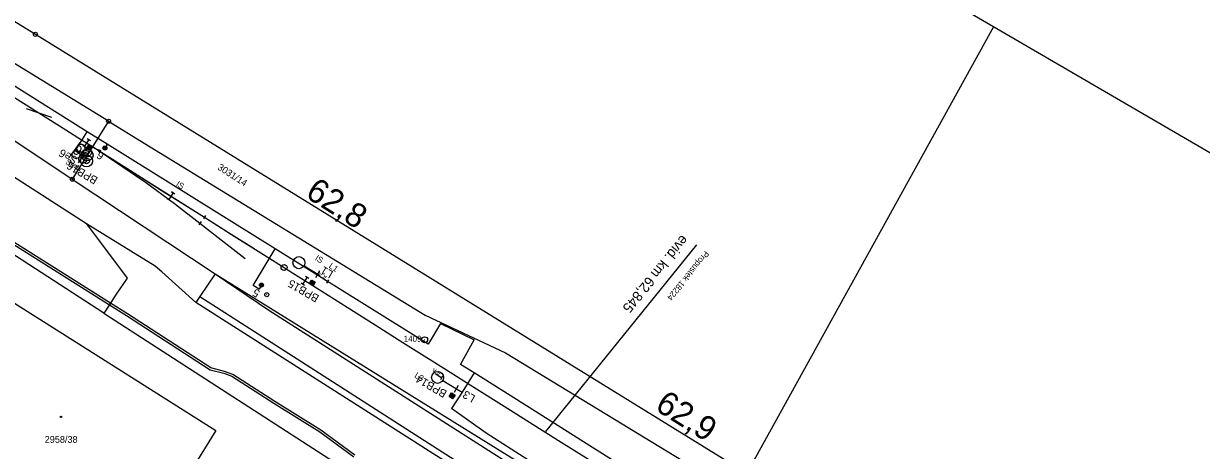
# Model space of a CAD drawing. Extents: x -621168 to -620292, y -1122748 to -1122069.
# Drawn here: x -620869 to -620574.6, y -1122402.8 to -1122296.3 of the extents above; entities that cross this region are included whole.
import ezdxf

# ---------------------------------------------------------------- set-up
doc = ezdxf.new("R2010")
doc.units = 0
for name, color, linetype in [('HranDP', 7, 'Continuous'), ('Hranice parcel', 7, 'Continuous'), ('Parcelní čísla', 7, 'Continuous'), ('Rámečky-tisk', 7, 'Continuous'), ('Vnitřní kresba', 7, 'Continuous'), ('Vrstva 1', 7, 'Continuous'), ('Vrstva 19', 7, 'Continuous'), ('Vrstva 2', 7, 'Continuous'), ('Vrstva 3', 7, 'Continuous'), ('Vrstva 6', 7, 'Continuous'), ('Vrstva 7', 7, 'Continuous'), ('Věcná břemena k části', 7, 'Continuous'), ('Značky bodu BP', 7, 'Continuous'), ('Značky budov', 7, 'Continuous')]:
    doc.layers.add(name, color=color, linetype=linetype)

msp = doc.modelspace()

# ---------------------------------------------------------------- linework, layer by layer
at = {"layer": 'HranDP'}
msp.add_line((-620856.79, -1122335.14), (-620821.12, -1122358.76), dxfattribs=at)
for points in [[(-620847.72, -1122320.67), (-620907.48, -1122284.08), (-620974.87, -1122244.96), (-620982.44, -1122240.65)], [(-620902.62, -1122306.44), (-620882.26, -1122318.28), (-620856.79, -1122335.14)], [(-620847.72, -1122320.67), (-620838.83, -1122326.12), (-620768.63, -1122369.09), (-620748.53, -1122378.52), (-620702.13, -1122406.7), (-620691.02, -1122413.66), (-620638.48, -1122446.57), (-620552.09, -1122499.2)], [(-620821.12, -1122358.76), (-620741.46, -1122408.09), (-620679.51, -1122447.56), (-620545.92, -1122532.26), (-620521.41, -1122548.27), (-620511.29, -1122557.64)]]:
    msp.add_lwpolyline(points, dxfattribs=at)
at = {"layer": 'Hranice parcel'}
for p, q in [((-620976.86, -1122231), (-620866.03, -1122298.98)), ((-620866.03, -1122298.98), (-620688.16, -1122408.5)), ((-620848.87, -1122368.55), (-620933.94, -1122313.6)), ((-620853.22, -1122346.25), (-620894.54, -1122319.77)), ((-620847.72, -1122320.67), (-620856.79, -1122335.14)), ((-620856.79, -1122335.14), (-620821.12, -1122358.76))]:
    msp.add_line(p, q, dxfattribs=at)
for points in [[(-620847.72, -1122320.67), (-620907.48, -1122284.08), (-620974.87, -1122244.96), (-620982.44, -1122240.65)], [(-620626.55, -1122297.1), (-620688.16, -1122408.5)], [(-620902.62, -1122306.44), (-620882.26, -1122318.28), (-620856.79, -1122335.14)], [(-620847.72, -1122320.67), (-620838.83, -1122326.12), (-620768.63, -1122369.09), (-620748.53, -1122378.52), (-620702.13, -1122406.7), (-620691.02, -1122413.66), (-620638.48, -1122446.57), (-620552.09, -1122499.2)], [(-620825.92, -1122365.89), (-620834.44, -1122358.28), (-620836.04, -1122356.85), (-620853.22, -1122346.25)], [(-620853.22, -1122346.25), (-620843.09, -1122359.81), (-620845.8, -1122363.88), (-620848.5, -1122367.99), (-620848.87, -1122368.55)], [(-620929.94, -1122378.34), (-620913.46, -1122352.29), (-620887.98, -1122368.3), (-620877.81, -1122374.71), (-620872.17, -1122365.51), (-620820.94, -1122397.9), (-620826.62, -1122407), (-620821.36, -1122410.31), (-620837.94, -1122436.41), (-620904.18, -1122394.6), (-620929.94, -1122378.34)], [(-620821.12, -1122358.76), (-620824.91, -1122364.39), (-620825.92, -1122365.89)], [(-620821.12, -1122358.76), (-620741.46, -1122408.09), (-620679.51, -1122447.56), (-620545.92, -1122532.26), (-620521.41, -1122548.27), (-620511.29, -1122557.64)], [(-620821.12, -1122358.76), (-620807.67, -1122367.84), (-620645.72, -1122471.03), (-620587.17, -1122509.18), (-620511.29, -1122557.64)], [(-620557.45, -1122536.96), (-620684.91, -1122455.63), (-620825.92, -1122365.89)], [(-620848.87, -1122368.55), (-620781.81, -1122411.87), (-620814.37, -1122462.27), (-620846.85, -1122512.55)]]:
    msp.add_lwpolyline(points, dxfattribs=at)
at = {"layer": 'Rámečky-tisk'}
msp.add_lwpolyline([(-620441.66, -1122748.16), (-620292.37, -1122491.41), (-621018.54, -1122069.17)], dxfattribs=at)
at = {"layer": 'Vnitřní kresba'}
for p, q in [((-620824.91, -1122364.39), (-620810.36, -1122373.73)), ((-620810.36, -1122373.73), (-620648.08, -1122477.56))]:
    msp.add_line(p, q, dxfattribs=at)
at = {"layer": 'Vrstva 1'}
for p, q in [((-620856.02, -1122328.01), (-620853.07, -1122323.34)), ((-620848.09, -1122326.43), (-620853.07, -1122323.34)), ((-620856.02, -1122328.01), (-620854.72, -1122328.89)), ((-620806.11, -1122352.53), (-620848.09, -1122326.43)), ((-620811.62, -1122361.65), (-620806.11, -1122352.53)), ((-620764.72, -1122371.2), (-620756.35, -1122375.21)), ((-620756.33, -1122383.52), (-620759.35, -1122388.27)), ((-620760.76, -1122387.45), (-620759.35, -1122388.27)), ((-620759.35, -1122388.27), (-620761.98, -1122392.4))]:
    msp.add_line(p, q, dxfattribs=at)
for points in [[(-620853.07, -1122323.34), (-620895.69, -1122296.63), (-620912.11, -1122286.23)], [(-620874.8, -1122312.5), (-620868.33, -1122316.57), (-620865.13, -1122318.58), (-620858.38, -1122322.84), (-620854.48, -1122325.28), (-620853.21, -1122326.08), (-620851.73, -1122327.01), (-620850.55, -1122327.76), (-620840.58, -1122334.05), (-620833.63, -1122338.43), (-620832.14, -1122339.37), (-620823.78, -1122344.63), (-620817.74, -1122348.46), (-620811.37, -1122352.45)], [(-620854.72, -1122328.89), (-620855.09, -1122329.44), (-620854.51, -1122329.81)], [(-620851.64, -1122327.08), (-620843.14, -1122332.43), (-620837.63, -1122335.92), (-620832.12, -1122339.39), (-620828.02, -1122341.97), (-620823.79, -1122344.63), (-620816.97, -1122348.94), (-620810.35, -1122353.09), (-620803.86, -1122357.18), (-620803.36, -1122357.5), (-620800.13, -1122359.53), (-620798.65, -1122360.46), (-620794.42, -1122363.12), (-620788.1, -1122367.1), (-620781.12, -1122371.5), (-620774.17, -1122375.88), (-620767.51, -1122380.06), (-620763.22, -1122382.76), (-620756.39, -1122387.05), (-620748.87, -1122391.78), (-620741.59, -1122396.35), (-620734.61, -1122400.75), (-620727.79, -1122405.03)], [(-620850.55, -1122327.76), (-620838.47, -1122335.9), (-620831.26, -1122341.18), (-620824.88, -1122346.1), (-620819.56, -1122350.3), (-620813.61, -1122354.97)], [(-620848.09, -1122326.43), (-620848.09, -1122326.43), (-620848.63, -1122327.36)], [(-620795.27, -1122359.26), (-620795.68, -1122359.01), (-620806.11, -1122352.53)], [(-620795.42, -1122358.82), (-620795.12, -1122359.01), (-620795.27, -1122359.26)], [(-620764.72, -1122371.2), (-620767.85, -1122376.3), (-620794.6, -1122359.68), (-620795.27, -1122359.26)], [(-620809.51, -1122361.58), (-620810.11, -1122362.57), (-620811.62, -1122361.65)], [(-620756.33, -1122383.52), (-620759.75, -1122381.36), (-620756.35, -1122375.21)], [(-620538.89, -1122521.21), (-620599.21, -1122483.22), (-620683.52, -1122429.44), (-620747.38, -1122389.13), (-620756.33, -1122383.52)], [(-620738.73, -1122407.89), (-620753.37, -1122398.54), (-620761.98, -1122392.4)]]:
    msp.add_lwpolyline(points, dxfattribs=at)
at = {"layer": 'Vrstva 19'}
msp.add_line((-620700.78, -1122351.5), (-620738.53, -1122398.14), dxfattribs=at)
at = {"layer": 'Vrstva 2'}
for p, q in [((-620853.74, -1122328.53), (-620855.29, -1122331.09)), ((-620852.78, -1122328.69), (-620854.51, -1122329.09)), ((-620852.5, -1122328.24), (-620854.45, -1122328.69)), ((-620852.38, -1122327.83), (-620854.23, -1122328.25)), ((-620852.28, -1122327.88), (-620853.83, -1122330.36)), ((-620853.2, -1122327.4), (-620851.84, -1122327.07)), ((-620853.13, -1122327.52), (-620851.85, -1122327.21)), ((-620853.1, -1122327.25), (-620852, -1122326.97)), ((-620853.01, -1122327.09), (-620852.16, -1122326.88)), ((-620852.97, -1122327.62), (-620851.95, -1122327.37)), ((-620852.91, -1122326.93), (-620852.32, -1122326.78)), ((-620852.82, -1122326.77), (-620852.48, -1122326.69)), ((-620852.81, -1122327.71), (-620852.05, -1122327.52)), ((-620852.72, -1122326.61), (-620852.64, -1122326.59)), ((-620852.65, -1122327.81), (-620852.14, -1122327.68)), ((-620852.49, -1122327.91), (-620852.24, -1122327.84)), ((-620852.28, -1122327.88), (-620851.73, -1122327.01)), ((-620852.28, -1122327.88), (-620852.28, -1122327.88)), ((-620848.14, -1122327.31), (-620849.13, -1122327.42)), ((-620848.2, -1122327.11), (-620849.11, -1122327.21)), ((-620848.16, -1122327.51), (-620849.07, -1122327.61)), ((-620848.38, -1122326.93), (-620848.97, -1122327)), ((-620848.29, -1122327.73), (-620848.88, -1122327.79)), ((-620853.07, -1122329.14), (-620854.47, -1122329.46)), ((-620853.35, -1122329.59), (-620854.34, -1122329.82)), ((-620853.63, -1122330.04), (-620854.09, -1122330.15)), ((-620824.58, -1122345.71), (-620825.19, -1122346.5)), ((-620823.51, -1122344.21), (-620824.04, -1122345.06)), ((-620798.85, -1122356.75), (-620795.42, -1122358.82)), ((-620795.94, -1122359.68), (-620794.91, -1122357.96)), ((-620809.82, -1122361.18), (-620809.6, -1122362.07)), ((-620809.63, -1122361.09), (-620809.39, -1122362.06)), ((-620809.43, -1122361.09), (-620809.21, -1122361.97)), ((-620809.2, -1122361.19), (-620809.05, -1122361.77)), ((-620796.1, -1122360.91), (-620797.46, -1122361.25)), ((-620796.18, -1122360.8), (-620797.45, -1122361.11)), ((-620796.33, -1122360.7), (-620797.35, -1122360.95)), ((-620796.2, -1122361.07), (-620797.3, -1122361.34)), ((-620796.49, -1122360.6), (-620797.26, -1122360.79)), ((-620796.65, -1122360.51), (-620797.16, -1122360.63)), ((-620796.29, -1122361.23), (-620797.14, -1122361.44)), ((-620796.81, -1122360.41), (-620797.06, -1122360.48)), ((-620809.97, -1122361.38), (-620809.83, -1122361.96)), ((-620796.39, -1122361.39), (-620796.98, -1122361.54)), ((-620796.49, -1122361.55), (-620796.82, -1122361.63)), ((-620796.58, -1122361.71), (-620796.66, -1122361.73)), ((-620764.19, -1122385.38), (-620760.76, -1122387.45)), ((-620761.28, -1122388.31), (-620760.25, -1122386.59)), ((-620761.17, -1122389.11), (-620762.54, -1122389.38)), ((-620761.23, -1122388.99), (-620762.52, -1122389.24)), ((-620761.39, -1122388.88), (-620762.42, -1122389.09)), ((-620761.27, -1122389.26), (-620762.38, -1122389.48)), ((-620761.54, -1122388.78), (-620762.31, -1122388.93)), ((-620761.37, -1122389.42), (-620762.23, -1122389.59)), ((-620761.7, -1122388.68), (-620762.21, -1122388.78)), ((-620761.85, -1122388.57), (-620762.11, -1122388.63)), ((-620761.48, -1122389.57), (-620762.07, -1122389.69)), ((-620761.58, -1122389.72), (-620761.92, -1122389.79)), ((-620761.68, -1122389.88), (-620761.76, -1122389.9))]:
    msp.add_line(p, q, dxfattribs=at)
for points in [[(-620852.69, -1122326.56), (-620851.79, -1122327.1), (-620852.33, -1122328), (-620853.23, -1122327.46)], [(-620852.69, -1122326.56), (-620851.79, -1122327.1), (-620852.33, -1122328), (-620853.23, -1122327.46)], [(-620796.61, -1122361.76), (-620797.51, -1122361.22), (-620796.97, -1122360.32), (-620796.07, -1122360.86)], [(-620796.61, -1122361.76), (-620797.51, -1122361.22), (-620796.97, -1122360.32), (-620796.07, -1122360.86)], [(-620761.72, -1122389.93), (-620762.59, -1122389.35), (-620762.01, -1122388.47), (-620761.13, -1122389.06)], [(-620761.72, -1122389.93), (-620762.59, -1122389.35), (-620762.01, -1122388.47), (-620761.13, -1122389.06)]]:
    msp.add_lwpolyline(points, close=True, dxfattribs=at)
msp.add_lwpolyline([(-620849.6, -1122328.08), (-620850.55, -1122327.76), (-620849.89, -1122328.51)], dxfattribs=at)
for centre, radius in [((-620853.06, -1122329.13), 1.46), ((-620848.63, -1122327.36), 0.5), ((-620853.23, -1122330.58), 1.5), ((-620853.23, -1122330.58), 0.7), ((-620800.13, -1122355.98), 1.5), ((-620809.51, -1122361.58), 0.5), ((-620765.47, -1122384.61), 1.5)]:
    msp.add_circle(centre, radius, dxfattribs=at)
msp.add_arc((-620853.05, -1122329.12), 1.46, 57.9828, 237.9436, dxfattribs=at)
at = {"layer": 'Vrstva 3'}
for p, q in [((-620868.31, -1122317.51), (-620861.96, -1122319.66)), ((-620852.68, -1122325.24), (-620853.74, -1122326.93)), ((-620853.1, -1122324.97), (-620852.25, -1122325.5)), ((-620854.16, -1122326.67), (-620853.32, -1122327.2)), ((-620833.1, -1122339.95), (-620832.25, -1122340.48)), ((-620833.07, -1122339.97), (-620832.22, -1122340.5)), ((-620831.61, -1122338.52), (-620832.67, -1122340.21)), ((-620831.58, -1122338.54), (-620832.65, -1122340.24)), ((-620832.03, -1122338.25), (-620831.18, -1122338.79)), ((-620832.01, -1122338.28), (-620831.16, -1122338.81)), ((-620799.61, -1122361.04), (-620798.76, -1122361.57)), ((-620798.12, -1122359.61), (-620799.18, -1122361.3)), ((-620798.54, -1122359.35), (-620797.69, -1122359.88))]:
    msp.add_line(p, q, dxfattribs=at)
at = {"layer": 'Vrstva 6'}
for p, q in [((-620856.04, -1122327.63), (-620857.21, -1122329.26)), ((-620854.88, -1122326), (-620856.04, -1122327.63)), ((-620794.6, -1122359.6), (-620792.93, -1122360.66)), ((-620793.19, -1122361.08), (-620792.66, -1122360.23)), ((-620766.11, -1122383.64), (-620764.44, -1122384.69)), ((-620764.7, -1122385.11), (-620764.17, -1122384.26))]:
    msp.add_line(p, q, dxfattribs=at)
for centre in [(-620855.81, -1122329.03), (-620854.65, -1122327.4), (-620853.02, -1122328.56), (-620854.18, -1122330.19)]:
    msp.add_ellipse(centre, major_axis=(0.814, -0.582), ratio=0.999505, dxfattribs=at)
at = {"layer": 'Vrstva 7'}
msp.add_line((-620808.23, -1122363.94), (-620808.14, -1122363.99), dxfattribs=at)
for centre, radius in [((-620803.86, -1122357.18), 0.75), ((-620808.18, -1122363.97), 0.5)]:
    msp.add_circle(centre, radius, dxfattribs=at)
at = {"layer": 'Věcná břemena k části'}
msp.add_lwpolyline([(-620940.9, -1122305.27), (-620939.94, -1122306.28), (-620932.68, -1122311.73), (-620917.76, -1122321.94), (-620897.11, -1122334.91), (-620871.42, -1122351.43), (-620847.51, -1122366.48), (-620847.24, -1122366.07), (-620871.16, -1122351.01), (-620896.85, -1122334.49), (-620917.48, -1122321.52), (-620932.38, -1122311.33), (-620939.6, -1122305.9), (-620940.4, -1122305.07), (-620940.78, -1122305.04)], close=True, dxfattribs=at)
msp.add_lwpolyline([(-620786.17, -1122404), (-620794.67, -1122397.82), (-620806.18, -1122390.67), (-620816.7, -1122383.9), (-620818.72, -1122383.12), (-620822.15, -1122382.27), (-620842.97, -1122368.76), (-620847.24, -1122366.07), (-620847.51, -1122366.48), (-620843.23, -1122369.18), (-620822.35, -1122382.73), (-620818.88, -1122383.6), (-620816.92, -1122384.34), (-620806.44, -1122391.09), (-620794.95, -1122398.24), (-620786.45, -1122404.42)], dxfattribs=at)
at = {"layer": 'Značky bodu BP'}
for centre, radius in [((-620866.03, -1122298.98), 0.5), ((-620866.03, -1122298.98), 0.0303), ((-620847.72, -1122320.67), 0.5), ((-620847.72, -1122320.67), 0.0303), ((-620856.79, -1122335.14), 0.5), ((-620856.79, -1122335.14), 0.0303), ((-620768.72, -1122375.23), 0.75), ((-620768.72, -1122375.23), 0.03)]:
    msp.add_circle(centre, radius, dxfattribs=at)
at = {"layer": 'Značky budov'}
msp.add_circle((-620859.61, -1122394.47), 0.175, dxfattribs=at)

# ---------------------------------------------------------------- texts
at = {"layer": 'Parcelní čísla'}
msp.add_text('3031/14', height=1.7, rotation=327, dxfattribs=at).set_placement((-620820.66, -1122332.56))
msp.add_text('2958/38', height=1.7, dxfattribs=at).set_placement((-620863.69, -1122400.95))
at = {"layer": 'Vrstva 19'}
for s, height, p in [('evid. km 62,845', 2.5, (-620704.49, -1122348.9)), ('Propustek 18224', 1.5, (-620698.65, -1122352.9))]:
    msp.add_text(s, height=height, rotation=230.7597, dxfattribs=at).set_placement(p)
at = {"layer": 'Vrstva 2'}
msp.add_text('6', height=2.5, rotation=147.9632, dxfattribs=at).set_placement((-620853.99, -1122327.35))
at = {"layer": 'Vrstva 3'}
for s, height, rotation, p in [('Se6', 2, 149.8236, (-620855.28, -1122329.88)), ('6', 2, 149.8236, (-620848.64, -1122328.75)), ('BPB16', 2, 149.8236, (-620850.23, -1122334.81)), ('IS', 1.5, 327.8592, (-620831.01, -1122336.74)), ('IS', 1.5, 327.7899, (-620796.27, -1122355.23)), ('L1', 2, 149.8236, (-620791.41, -1122358.28)), ('BPB15', 2, 149.8236, (-620794.92, -1122364.27)), ('5', 2, 148.8786, (-620809.69, -1122363.11)), ('BPB14', 2, 149.8236, (-620762.97, -1122388.1)), ('L3', 2, 149.8236, (-620755.87, -1122389.29))]:
    msp.add_text(s, height=height, rotation=rotation, dxfattribs=at).set_placement(p)
at = {"layer": 'Vrstva 6'}
for s, height, rotation, p in [('Se4', 1.5, 327.8625, (-620858.66, -1122331.2)), ('  A A ', 1, 147.7824, (-620792.39, -1122359.81)), ('L1', 1.5, 327.7824, (-620792.81, -1122357.16)), ('L3', 1.5, 327.8824, (-620771.42, -1122384.51)), ('  A A ', 1, 147.8824, (-620763.9, -1122383.84))]:
    msp.add_text(s, height=height, rotation=rotation, dxfattribs=at).set_placement(p)
at = {"layer": 'Vrstva 7'}
for s, rotation, p in [('62,8', 327.7881, (-620798.8, -1122339.47)), ('62,9', 327.8519, (-620711.42, -1122392.58))]:
    msp.add_text(s, height=6, rotation=rotation, dxfattribs=at).set_placement(p)
at = {"layer": 'Značky bodu BP'}
msp.add_text('1409', height=1.5, dxfattribs=at).set_placement((-620773.97, -1122375.73))

doc.saveas('drawing.dxf')
